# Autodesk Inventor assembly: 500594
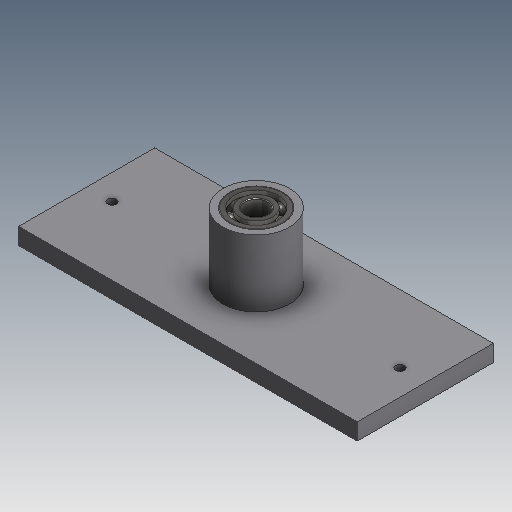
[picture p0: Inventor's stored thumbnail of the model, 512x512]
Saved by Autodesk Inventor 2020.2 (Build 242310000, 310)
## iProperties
Created: 2000-02
Part Number: 500594
Document SubType Name: Assembly
Designer: glanglot
Mass: 3059.14 g
Surface Area: 834.298 cm^2
Volume: 390.674 cm^3
Density: 7.83042 g/cm^3
Control State: 0
Checked Out: False
Master: False
Shininess: 0.0
Length Units: 11269
Angle Units: 11279
Time Units: 11290
Mass Units: 11283
Length Display Precision: 3
Angle Display Precision: 2
Compacted: True
Dimensions: 254x62,5x102 mm
Mass: 3,059 kg
Density: 0.0
Volumn: 0.0
Area: 0.0
PropertySet Name: Model Information
Author: glanglot
Revision Number: -
Title: 500594
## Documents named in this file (4)
- D:\07 - DEMODATEN\OTX 2019 - Dataset - UPDATE - Dez2019\Designs\07-Packing machine\500594.iam
- D:\07 - DEMODATEN\OTX 2019 - Dataset - UPDATE - Dez2019\Designs\07-Packing machine\Parts\ADSK-011553.ipt
- D:\07 - DEMODATEN\OTX 2019 - Dataset - UPDATE - Dez2019\Designs\07-Packing machine\Parts\ADSK-011554.ipt
- D:\07 - DEMODATEN\OTX 2019 - Dataset - UPDATE - Dez2019\Content Center Files\de-DE\DIN 625 SKF(5)\DIN 625 SKF - SKF 6203-2RSH.ipt
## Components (3 placed, 3 different names)
1. ADSK-011553:1
2. ADSK-011554:1
3. DIN 625 SKF- beidseitig abgedichtet SKF 6203-2RSH:1
